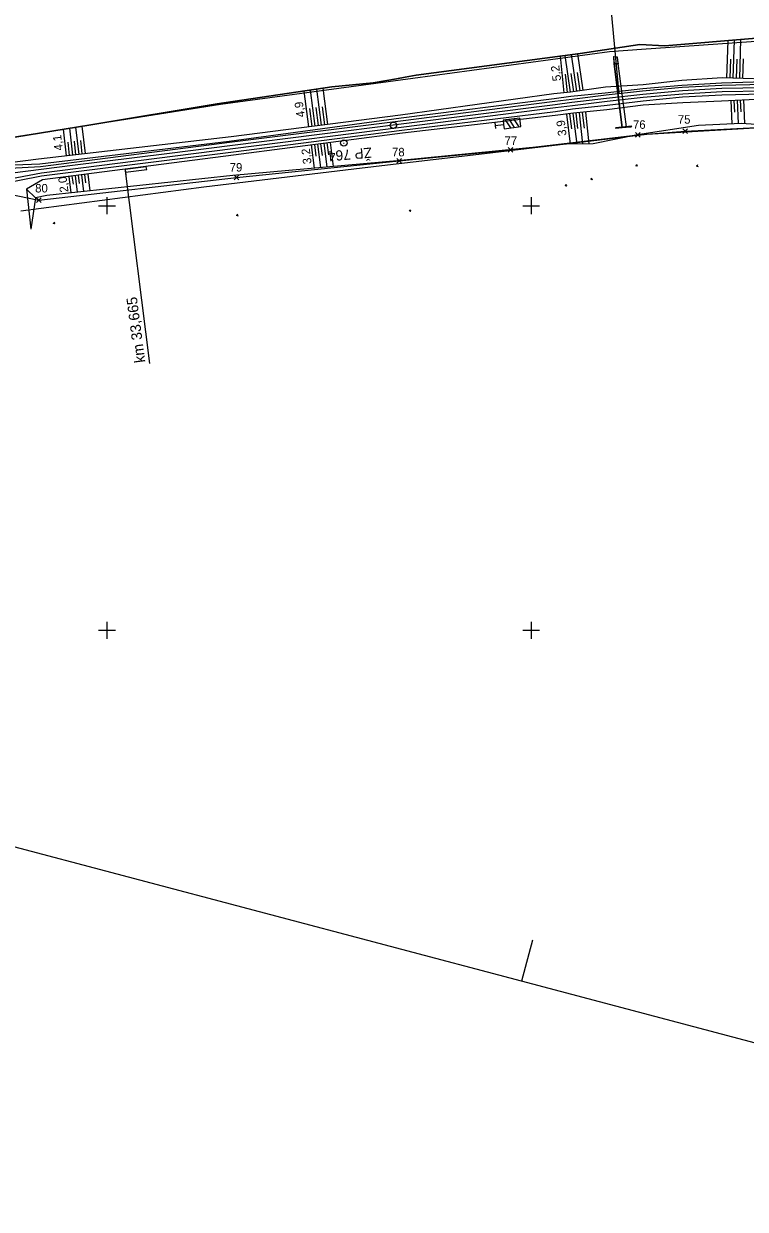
# Model space of a CAD drawing. Extents: x -805011 to -803920, y -1150790 to -1150234.
# Drawn here: x -804519.6 to -804349.5, y -1150736.4 to -1150457.1 of the extents above; entities that cross this region are included whole.
import ezdxf

# ---------------------------------------------------------------- set-up
doc = ezdxf.new("R2010")
doc.units = 0
for name, color, linetype in [('0381KM032-037P - Vrstva 1', 7, 'Continuous'), ('0381KM032-037P - Vrstva 17', 7, 'Continuous'), ('0381KM032-037P - Vrstva 19', 7, 'Continuous'), ('0381KM032-037P - Vrstva 4', 7, 'Continuous'), ('0381KM032-037P - Vrstva 48', 7, 'Continuous'), ('0381KM032-037P - Vrstva 49', 7, 'Continuous'), ('0381KM032-037P - Vrstva 7', 7, 'Continuous'), ('0381KM032-037P - Vrstva 9', 7, 'Continuous'), ('Default', 7, 'Continuous'), ('formát', 7, 'Continuous'), ('hran DP - hran DP', 7, 'Continuous'), ('krizky_1000 - Vrstva 1', 7, 'Continuous'), ('PSR_C2_2_Lomove_body_Vimperk - Vrstva 60', 7, 'Continuous'), ('PSR_C2_2_trasa_Vimperk - Kabelová trasa', 7, 'Continuous'), ('vyt_sit - stávající', 7, 'Continuous')]:
    doc.layers.add(name, color=color, linetype=linetype)

msp = doc.modelspace()

# ---------------------------------------------------------------- linework, layer by layer
at = {"layer": '0381KM032-037P - Vrstva 1'}
for points in [[(-804345.19, -1150472.22), (-804355.1, -1150472.39), (-804364.37, -1150472.93), (-804373.68, -1150473.77), (-804382.25, -1150474.73), (-804390.38, -1150475.71), (-804394.38, -1150476.22)], [(-804394.38, -1150476.22), (-804430.66, -1150480.81), (-804470.38, -1150485.81), (-804485.9, -1150487.74)], [(-804485.9, -1150487.74), (-804508.11, -1150490.55), (-804529.67, -1150493.3), (-804537.63, -1150494.31), (-804546.61, -1150495.46), (-804554.2, -1150496.42), (-804564.05, -1150497.67), (-804586.01, -1150500.48), (-804607.92, -1150503.26), (-804630.35, -1150506.11), (-804652.65, -1150508.9), (-804675.7, -1150511.78), (-804698.85, -1150514.71), (-804701.61, -1150515.06), (-804722.18, -1150517.67), (-804729.05, -1150518.54), (-804735.1, -1150519.31), (-804744.56, -1150520.5), (-804767.65, -1150523.46), (-804791, -1150526.42)]]:
    msp.add_lwpolyline(points, dxfattribs=at)
at = {"layer": '0381KM032-037P - Vrstva 17'}
for points in [[(-804368.54, -1150462.33), (-804374.42, -1150462.03), (-804388.45, -1150464.13), (-804427.08, -1150469.25), (-804429.72, -1150469.73), (-804431.75, -1150470.1), (-804437.24, -1150471.08), (-804446.96, -1150472.02), (-804473.97, -1150476), (-804503.76, -1150480.94), (-804524.61, -1150484.28), (-804530.6, -1150485.02), (-804536.33, -1150485.99), (-804541.81, -1150485.21), (-804546.58, -1150482.25), (-804551.41, -1150478.74), (-804558.4, -1150472.14)], [(-804328.85, -1150461.67), (-804338.71, -1150460.38), (-804346.87, -1150460.56), (-804368.54, -1150462.33)]]:
    msp.add_lwpolyline(points, dxfattribs=at)
at = {"layer": '0381KM032-037P - Vrstva 19'}
for p, q in [((-804384.94, -1150412.13), (-804379.37, -1150473.64)), ((-804380.55, -1150464.84), (-804380.55, -1150464.84)), ((-804378.59, -1150481.54), (-804380.47, -1150466.54)), ((-804380.44, -1150466.61), (-804378.59, -1150481.59)), ((-804379.54, -1150466.49), (-804379.54, -1150466.49)), ((-804379.54, -1150466.49), (-804377.61, -1150481.41)), ((-804378.59, -1150481.59), (-804377.64, -1150481.48))]:
    msp.add_line(p, q, dxfattribs=at)
for points in [[(-804380.55, -1150464.84), (-804380.57, -1150464.89), (-804380.47, -1150466.54)], [(-804380.44, -1150466.61), (-804380.55, -1150464.84), (-804379.8, -1150464.93), (-804379.51, -1150466.55)], [(-804379.8, -1150464.93), (-804379.76, -1150464.9), (-804379.54, -1150466.49)], [(-804379.51, -1150466.55), (-804379.54, -1150466.49), (-804380.47, -1150466.54), (-804380.44, -1150466.61), (-804379.51, -1150466.55)], [(-804379.54, -1150466.49), (-804380.47, -1150466.54), (-804380.47, -1150466.54)]]:
    msp.add_lwpolyline(points, dxfattribs=at)
for points in [[(-804380.55, -1150464.84), (-804380.55, -1150464.84)], [(-804378.59, -1150481.54), (-804377.61, -1150481.41), (-804377.64, -1150481.48), (-804376.42, -1150481.39), (-804376.29, -1150481.28), (-804380.1, -1150481.67), (-804380.08, -1150481.76), (-804378.59, -1150481.59)]]:
    msp.add_lwpolyline(points, close=True, dxfattribs=at)
at = {"layer": '0381KM032-037P - Vrstva 4'}
for p, q in [((-804515.79, -1150490.21), (-804529.7, -1150490.74)), ((-804515.61, -1150490.8), (-804529.7, -1150491.57)), ((-804515.43, -1150492.3), (-804529.48, -1150494.97)), ((-804515.43, -1150492.3), (-804515.43, -1150492.3)), ((-804515.37, -1150493.06), (-804529.38, -1150495.79)), ((-804515.37, -1150493.06), (-804515.37, -1150493.06))]:
    msp.add_line(p, q, dxfattribs=at)
for points in [[(-804225.7, -1150511.47), (-804233.93, -1150505.38), (-804241.84, -1150500.35), (-804251.18, -1150495.03), (-804260.27, -1150490.25), (-804271.39, -1150485.02), (-804282.1, -1150481.42), (-804291.28, -1150478.15), (-804302, -1150475.62), (-804311.22, -1150473.82), (-804320.47, -1150472.35), (-804331.17, -1150471.28), (-804341.36, -1150470.84), (-804345.11, -1150470.79), (-804355.15, -1150471.09), (-804364.49, -1150471.64), (-804373.72, -1150472.46), (-804382.56, -1150473.46), (-804390.64, -1150474.3), (-804394.58, -1150474.82), (-804430.68, -1150479.4), (-804471.16, -1150484.87), (-804515.79, -1150490.21)], [(-804222.47, -1150514.31), (-804225.93, -1150511.88), (-804233.81, -1150506.22), (-804242.12, -1150500.85), (-804250.57, -1150495.96), (-804260.44, -1150490.89), (-804271.28, -1150486.07), (-804282.21, -1150481.99), (-804291.28, -1150479.14), (-804302.11, -1150476.36), (-804311.33, -1150474.54), (-804320.55, -1150473.14), (-804330.83, -1150472.06), (-804341.5, -1150471.52), (-804345.16, -1150471.47), (-804355.1, -1150471.64), (-804364.39, -1150472.17), (-804373.73, -1150473.02), (-804382.33, -1150473.97), (-804390.45, -1150474.97), (-804394.45, -1150475.48), (-804430.79, -1150480.07), (-804470.48, -1150485.06), (-804515.61, -1150490.8)], [(-804223.37, -1150515.97), (-804226.85, -1150513.1), (-804234.67, -1150507.48), (-804242.93, -1150502.16), (-804251.31, -1150497.29), (-804261.13, -1150492.25), (-804271.85, -1150487.49), (-804282.71, -1150483.42), (-804291.73, -1150480.59), (-804302.46, -1150477.85), (-804311.66, -1150476.01), (-804320.71, -1150474.65), (-804330.94, -1150473.58), (-804341.55, -1150473.05), (-804345.16, -1150472.99), (-804355.02, -1150473.16), (-804364.28, -1150473.69), (-804373.57, -1150474.51), (-804382.12, -1150475.46), (-804390.26, -1150476.46), (-804394.25, -1150476.96), (-804430.61, -1150481.56), (-804470.33, -1150486.56), (-804515.43, -1150492.3)], [(-804235.83, -1150507.71), (-804243.11, -1150502.63), (-804252.43, -1150497.68), (-804261.4, -1150493.06), (-804272.11, -1150488.47), (-804283.06, -1150484.22), (-804291.82, -1150481.32), (-804302.89, -1150478.85), (-804311.92, -1150476.81), (-804320.92, -1150475.47), (-804331.06, -1150474.34), (-804341.56, -1150473.81), (-804345.45, -1150473.75), (-804355.04, -1150473.96), (-804364.32, -1150474.45), (-804373.64, -1150475.34), (-804382.1, -1150476.35), (-804390.24, -1150477.29), (-804394.24, -1150477.85), (-804430.45, -1150482.3), (-804470.19, -1150487.36), (-804515.37, -1150493.06)]]:
    msp.add_lwpolyline(points, dxfattribs=at)
at = {"layer": '0381KM032-037P - Vrstva 48'}
for p, q in [((-804353.86, -1150469.92), (-804353.59, -1150461.11)), ((-804352.36, -1150469.97), (-804352.08, -1150460.99)), ((-804350.86, -1150470.01), (-804350.58, -1150460.86)), ((-804392.19, -1150473.4), (-804393.06, -1150464.74)), ((-804390.7, -1150473.25), (-804391.97, -1150464.6)), ((-804389.22, -1150473.03), (-804390.48, -1150464.4)), ((-804387.73, -1150472.81), (-804389, -1150464.2)), ((-804353.11, -1150469.95), (-804352.97, -1150465.5)), ((-804351.61, -1150469.99), (-804351.47, -1150465.46)), ((-804350.11, -1150470.04), (-804349.97, -1150465.42)), ((-804391.45, -1150473.33), (-804391.88, -1150468.99)), ((-804389.96, -1150473.14), (-804390.59, -1150468.82)), ((-804388.47, -1150472.92), (-804389.11, -1150468.61)), ((-804452.39, -1150481.41), (-804453.47, -1150472.98)), ((-804450.91, -1150481.22), (-804451.98, -1150472.76)), ((-804449.42, -1150481.03), (-804450.5, -1150472.54)), ((-804447.93, -1150480.84), (-804449.02, -1150472.32)), ((-804352.98, -1150475.24), (-804352.72, -1150480.7)), ((-804352.23, -1150475.2), (-804352.1, -1150477.93)), ((-804351.48, -1150475.16), (-804351.22, -1150480.62)), ((-804350.73, -1150475.13), (-804350.6, -1150477.86)), ((-804349.98, -1150475.09), (-804349.71, -1150480.65)), ((-804451.65, -1150481.31), (-804452.19, -1150477.09)), ((-804450.16, -1150481.12), (-804450.7, -1150476.89)), ((-804448.67, -1150480.93), (-804449.22, -1150476.68)), ((-804391.67, -1150478.44), (-804390.78, -1150485.49)), ((-804390.93, -1150478.35), (-804390.48, -1150481.91)), ((-804390.19, -1150478.25), (-804389.27, -1150485.47)), ((-804389.44, -1150478.17), (-804389.05, -1150481.81)), ((-804388.69, -1150478.09), (-804387.9, -1150485.45)), ((-804387.95, -1150478.01), (-804387.55, -1150481.72)), ((-804387.2, -1150477.93), (-804386.39, -1150485.42)), ((-804508.03, -1150488.07), (-804508.76, -1150481.74)), ((-804506.54, -1150487.9), (-804507.28, -1150481.5)), ((-804505.05, -1150487.73), (-804505.79, -1150481.27)), ((-804509.52, -1150488.25), (-804510.24, -1150481.98)), ((-804505.79, -1150487.81), (-804506.16, -1150484.6)), ((-804508.77, -1150488.16), (-804509.14, -1150485.01)), ((-804507.28, -1150487.99), (-804507.65, -1150484.8)), ((-804451.85, -1150485.69), (-804451.15, -1150491.14)), ((-804451.1, -1150485.59), (-804450.75, -1150488.33)), ((-804450.36, -1150485.49), (-804449.65, -1150491.01)), ((-804449.62, -1150485.4), (-804449.26, -1150488.17)), ((-804448.87, -1150485.3), (-804448.15, -1150490.87)), ((-804448.13, -1150485.21), (-804447.77, -1150488.01)), ((-804447.39, -1150485.11), (-804446.66, -1150490.74)), ((-804508.23, -1150493.02), (-804507.98, -1150494.94)), ((-804507.49, -1150492.92), (-804506.99, -1150496.79)), ((-804506.75, -1150492.83), (-804506.49, -1150494.77)), ((-804506, -1150492.73), (-804505.49, -1150496.63)), ((-804505.26, -1150492.63), (-804505.01, -1150494.59)), ((-804504.52, -1150492.53), (-804504, -1150496.47)), ((-804508.98, -1150493.12), (-804508.48, -1150496.95))]:
    msp.add_line(p, q, dxfattribs=at)
at = {"layer": '0381KM032-037P - Vrstva 49'}
for p, q in [((-804375.44, -1150490.42), (-804374.98, -1150490.64)), ((-804375.1, -1150490.3), (-804375.32, -1150490.76)), ((-804361.14, -1150490.51), (-804360.68, -1150490.73)), ((-804360.8, -1150490.39), (-804361.02, -1150490.85)), ((-804392.06, -1150495.11), (-804391.6, -1150495.33)), ((-804391.72, -1150494.99), (-804391.94, -1150495.45)), ((-804386.04, -1150493.59), (-804385.58, -1150493.81)), ((-804385.7, -1150493.47), (-804385.92, -1150493.93)), ((-804518.94, -1150496.06), (-804516.85, -1150498.14)), ((-804428.79, -1150501.05), (-804428.33, -1150501.27)), ((-804428.45, -1150500.93), (-804428.67, -1150501.39)), ((-804512.71, -1150504), (-804512.25, -1150504.22)), ((-804512.37, -1150503.88), (-804512.59, -1150504.34)), ((-804469.54, -1150502.14), (-804469.08, -1150502.36)), ((-804469.2, -1150502.02), (-804469.42, -1150502.48))]:
    msp.add_line(p, q, dxfattribs=at)
for points in [[(-804541.81, -1150485.21), (-804536.33, -1150485.99), (-804530.6, -1150485.02), (-804524.61, -1150484.28), (-804503.76, -1150480.94), (-804473.97, -1150476), (-804446.96, -1150472.02), (-804437.24, -1150471.08), (-804431.75, -1150470.1), (-804429.72, -1150469.73), (-804427.08, -1150469.25), (-804388.45, -1150464.13), (-804374.42, -1150462.03), (-804368.54, -1150462.33), (-804346.87, -1150460.56), (-804338.71, -1150460.38), (-804328.85, -1150461.67), (-804323.06, -1150462.29), (-804320.34, -1150463.27)], [(-804345.1, -1150470.19), (-804354.95, -1150469.89), (-804364.53, -1150470.46), (-804373.6, -1150471.54), (-804382.52, -1150472.05), (-804390.77, -1150473.26), (-804394.69, -1150473.65), (-804430.78, -1150478.65), (-804470.67, -1150483.74), (-804516.1, -1150489.01), (-804529.7, -1150490.74)], [(-804226.97, -1150514.32), (-804233.94, -1150510.78), (-804236.52, -1150508.57), (-804243.93, -1150503.82), (-804252.72, -1150498.82), (-804262.25, -1150494.6), (-804273.33, -1150489.4), (-804283.59, -1150485.01), (-804292.89, -1150482.47), (-804303.02, -1150479.68), (-804312.2, -1150478.16), (-804321.12, -1150476.62), (-804331.14, -1150475.24), (-804341.8, -1150475.06), (-804345.41, -1150474.87), (-804355.14, -1150475.34), (-804364.22, -1150475.73), (-804373.58, -1150476.33), (-804382.14, -1150477.38), (-804390.01, -1150478.23), (-804394.36, -1150478.78), (-804430.35, -1150482.91), (-804470.16, -1150488.05), (-804515.21, -1150493.93)], [(-804276.15, -1150497.56), (-804284.03, -1150490.16), (-804299.15, -1150485.83), (-804306.89, -1150483.98), (-804317.28, -1150482.7), (-804327.05, -1150481.84), (-804338.6, -1150481.41), (-804350.55, -1150480.59), (-804360.54, -1150481.11), (-804374.96, -1150483.29), (-804385.39, -1150485.41), (-804391.71, -1150485.5), (-804430.73, -1150489.32), (-804470.3, -1150492.85), (-804514.17, -1150497.56)], [(-804515.21, -1150493.93), (-804518.94, -1150496.06), (-804517.94, -1150505.51)], [(-804514.17, -1150497.56), (-804516.85, -1150498.14), (-804517.94, -1150505.51)]]:
    msp.add_lwpolyline(points, dxfattribs=at)
at = {"layer": '0381KM032-037P - Vrstva 7'}
for p, q in [((-804408.58, -1150480.36), (-804408.4, -1150481.84)), ((-804406.13, -1150479.8), (-804404.89, -1150481.66)), ((-804403.9, -1150481.54), (-804405.14, -1150479.68)), ((-804404.15, -1150479.55), (-804402.91, -1150481.41))]:
    msp.add_line(p, q, dxfattribs=at)
msp.add_lwpolyline([(-804408.49, -1150481.1), (-804406.51, -1150480.85), (-804406.38, -1150481.85), (-804402.41, -1150481.35), (-804402.66, -1150479.37), (-804406.63, -1150479.86), (-804406.51, -1150480.85)], dxfattribs=at)
msp.add_circle((-804432.47, -1150481.04), 0.75, dxfattribs=at)
at = {"layer": '0381KM032-037P - Vrstva 9'}
for p, q in [((-804490.7, -1150490.86), (-804495.66, -1150491.5)), ((-804495.66, -1150491.5), (-804495.58, -1150492.1)), ((-804489.86, -1150537.15), (-804495.62, -1150491.8)), ((-804495.58, -1150492.1), (-804490.62, -1150491.45)), ((-804495.58, -1150492.1), (-804495.5, -1150492.69)), ((-804490.62, -1150491.45), (-804490.7, -1150490.86))]:
    msp.add_line(p, q, dxfattribs=at)
at = {"layer": 'formát'}
for p, q in [((-804402.28, -1150682.7), (-805011.32, -1150521.54)), ((-804399.72, -1150673.03), (-804402.28, -1150682.7)), ((-804399.72, -1150673.03), (-804402.28, -1150682.7)), ((-804199.27, -1150736.42), (-804402.28, -1150682.7))]:
    msp.add_line(p, q, dxfattribs=at)
at = {"layer": 'hran DP - hran DP'}
for p, q in [((-804374.01, -1150463.14), (-804345.91, -1150461.18)), ((-804427.86, -1150469.92), (-804381.52, -1150463.67)), ((-804381.52, -1150463.67), (-804374.01, -1150463.14)), ((-804473.24, -1150476.04), (-804427.86, -1150469.92)), ((-804532.83, -1150485.53), (-804473.24, -1150476.04)), ((-804340.86, -1150481.33), (-804372.75, -1150483.24)), ((-804383.87, -1150484.55), (-804413.66, -1150488.07)), ((-804372.75, -1150483.24), (-804383.87, -1150484.55)), ((-804413.66, -1150488.07), (-804432.51, -1150490.32)), ((-804441.78, -1150491.42), (-804477.16, -1150495.64)), ((-804432.51, -1150490.32), (-804441.78, -1150491.42)), ((-804477.16, -1150495.64), (-804520.26, -1150501.29))]:
    msp.add_line(p, q, dxfattribs=at)
at = {"layer": 'krizky_1000 - Vrstva 1'}
for points in [[(-804500, -1150498), (-804500, -1150502)], [(-804400, -1150498), (-804400, -1150502)], [(-804502, -1150500), (-804498, -1150500)], [(-804402, -1150500), (-804398, -1150500)], [(-804500, -1150598), (-804500, -1150602)], [(-804400, -1150598), (-804400, -1150602)], [(-804502, -1150600), (-804498, -1150600)], [(-804402, -1150600), (-804398, -1150600)]]:
    msp.add_lwpolyline(points, dxfattribs=at)
at = {"layer": 'PSR_C2_2_Lomove_body_Vimperk - Vrstva 60'}
for p, q in [((-804375.39, -1150483.87), (-804374.29, -1150482.77)), ((-804374.29, -1150483.87), (-804375.39, -1150482.77)), ((-804364.23, -1150483.02), (-804363.13, -1150481.92)), ((-804363.13, -1150483.02), (-804364.23, -1150481.92)), ((-804405.39, -1150487.4), (-804404.29, -1150486.3)), ((-804404.29, -1150487.4), (-804405.39, -1150486.3)), ((-804431.65, -1150489.97), (-804430.55, -1150488.87)), ((-804430.55, -1150489.97), (-804431.65, -1150488.87)), ((-804470.01, -1150493.88), (-804468.91, -1150492.78)), ((-804468.91, -1150493.88), (-804470.01, -1150492.78)), ((-804516.56, -1150499.24), (-804515.46, -1150498.14)), ((-804515.46, -1150499.24), (-804516.56, -1150498.14))]:
    msp.add_line(p, q, dxfattribs=at)
at = {"layer": 'PSR_C2_2_trasa_Vimperk - Kabelová trasa'}
msp.add_lwpolyline([(-804529.08, -1150496.27), (-804528.3, -1150496.2), (-804516.01, -1150498.69), (-804469.46, -1150493.33), (-804431.1, -1150489.42), (-804404.84, -1150486.85), (-804374.84, -1150483.32), (-804363.68, -1150482.47), (-804347.01, -1150481.54), (-804340.82, -1150481.2), (-804326.33, -1150481.6), (-804317.79, -1150482), (-804308.33, -1150484.14), (-804289, -1150488.51)], dxfattribs=at)
at = {"layer": 'vyt_sit - stávající'}
msp.add_line((-804444.21, -1150485.23), (-804444.1, -1150485.23), dxfattribs=at)
msp.add_circle((-804444.16, -1150485.23), 0.756, dxfattribs=at)

# ---------------------------------------------------------------- texts
at = {"layer": '0381KM032-037P - Vrstva 48'}
for s, rotation, p in [('5,2', 97.5493, (-804392.93, -1150470.51)), ('4,9', 98.3966, (-804453.3, -1150479.03)), ('3,9', 97.2061, (-804391.65, -1150483.43)), ('4,1', 96.6169, (-804510.37, -1150486.87)), ('3,2', 97.3569, (-804451.73, -1150490.07)), ('2,0', 97.4363, (-804509.04, -1150496.72))]:
    msp.add_text(s, height=2, rotation=rotation, dxfattribs=at).set_placement(p)
at = {"layer": '0381KM032-037P - Vrstva 9'}
msp.add_text('km 33,665', height=2.5, rotation=97.4056, dxfattribs=at).set_placement((-804490.93, -1150536.84))
at = {"layer": 'Default'}
for s, p in [('75', (-804365.44, -1150480.67)), ('76', (-804376.01, -1150481.88)), ('77', (-804406.28, -1150485.67)), ('78', (-804432.8, -1150488.36)), ('79', (-804471.06, -1150491.95)), ('80', (-804516.9, -1150496.88))]:
    msp.add_text(s, height=2, dxfattribs=at).set_placement(p)
at = {"layer": 'vyt_sit - stávající'}
msp.add_text('ŽP 764', height=2.4, rotation=185, dxfattribs=at).set_placement((-804437.66, -1150486.27))

doc.saveas('drawing.dxf')
